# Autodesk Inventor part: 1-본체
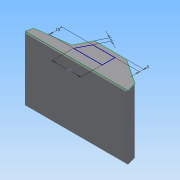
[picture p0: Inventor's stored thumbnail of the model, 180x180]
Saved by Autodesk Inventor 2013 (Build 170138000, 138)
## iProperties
Created: 2015-06
Part Number: 1-본체
Material: 일반
Document SubType Name: Modeling
Designer: Administrator
Density: 1 g/cm^3
Author: Administrator
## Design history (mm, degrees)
sketch "스케치1"
  geometry: L1 (0, 0)-(-122, 0); L2 (-122, 0)-(-119.856, 8); L3 (-119.856, 8)-(-80, 13.463); L4 (-80, 13.463)-(-70.99, 31); L5 (-70.99, 31)-(-32.947, 31); L6 (-32.947, 31)-(-2.947, 11); L7 (-2.947, 11)-(0, 0)
  constraints: 14 end point, 1 horizontal, 1 parallel
  dimensions: "d0" = 122 distance of L1.start L1.end; "d1" = 8 vertical distance of L1.end L2.end; "d2" = 42 horizontal distance of L3.end L1.end; "d6" = 105 deg angle of L1 L2; "d7" = 125 deg angle of L4 L3; "d8" = 20 vertical distance of L6.end L5.end; "d9" = 105 deg angle of L1 L7; "d10" = 31 vertical distance of L5.end L1.start; "d11" = 30 horizontal distance of L5.end L6.end; "d12" = 42.1946 deg angle of L4 L7
extrude "돌출1" new body sketch "스케치1" stored distance "d13" = 76; taper "d14" = 0 deg
sketch "스케치2"
  geometry: L1 (122, -76)-(122, 0) reference; L2 (0, 0)-(122, 0) reference; L3 (0, 0)-(0, -76) reference; L4 (122, -76)-(0, -76) reference; L5 (121, -1)-(121, -75); L6 (121, -75)-(1, -75); L7 (1, -75)-(1, -1); L8 (1, -1)-(121, -1); 1 further point
  constraints: 8 end point, 3 other
  dimensions: "d15" = 1 distance between parallel lines of L8 L2
extrude "돌출2" join sketch "스케치2" distance "d16" = 1; taper "d17" = 0 deg
sketch "스케치3"
  geometry: L1 (0, 0)-(0, 76) reference; L2 (7.79, 51)-(27.79, 51); L3 (27.79, 51)-(27.79, 25); L4 (27.79, 25)-(7.79, 25); L5 (7.79, 25)-(7.79, 51); L6 (-3.21, 0)-(-3.21, 76) reference; 3 further points
  constraints: 8 end point, 2 midpoint, 2 parallel, 1 horizontal, 1 horizontal alignment, 1 perpendicular
  dimensions: "d18" = 20 distance of L2.start L2.end; "d20" = 26 distance of L4.end L2.start; "d21" = 11 distance between parallel lines of L5 L6
extrude "돌출3" join sketch "스케치3" distance "d22" = 5; taper "d23" = 0 deg
sketch "스케치4"
  geometry: L1 (-122, 0)-(0, 0) reference; L2 (0, 0)-(-2.947, 11) reference; L3 (-2.947, 11)-(-32.947, 31) reference; L4 (-32.947, 31)-(-70.99, 31) reference; L5 (-70.99, 31)-(-80, 13.463) reference; L6 (-80, 13.463)-(-119.856, 8) reference; L7 (-119.856, 8)-(-122, 0) reference; L8 (-67.937, 26)-(-75.644, 11); L9 (-67.937, 26)-(-41.644, 26); L10 (-41.644, 26)-(-41.644, 11); L11 (-41.644, 11)-(-75.644, 11)
  constraints: 8 end point, 3 parallel, 1 perpendicular
  dimensions: "d24" = 15 vertical distance of L8.end L8.start; "d26" = 5 distance between parallel lines of L9 L4; "d27" = 5 distance between parallel lines of L8 L5; "d28" = 34 distance of L10.end L8.end
node "솔리드1"
